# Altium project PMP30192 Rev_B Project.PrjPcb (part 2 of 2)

## Sheet PMP30192 Rev_B Modulator Schematic.SchDoc: PFC + LLC Modulator
size 431 x 279 mm; Date: Not shown in title block; ApprovedBy: Not shown in title block; CheckedBy: Not shown in title block; Author: Not shown in title block; CompanyName: Not shown in title block; DrawnBy: R. Scibilia; Engineer: Not shown in title block; Organization: Not shown in title block; Address1: Not shown in title block; Address2: Not shown in title block; Address3: Not shown in title block; Address4: Not shown in title block; DocumentNumber: 1; Revision: Use project parameter SCH_Rev; SheetNumber: 2; SheetTotal: 3; PageSetup: Record=PageOptions¦CenterHorizontal=True¦CenterVertical=True¦PrintScale=1.00¦XCorrection=1.00¦YCorrection=1.00¦PrintKind=0¦BorderSize=5000000¦LeftOffset=0¦BottomOffset=0¦Orientation=2¦PaperLength=1000¦PaperWidth=1000¦Scale=100¦PaperSource=15¦PrintQuality=600¦MediaType=1¦DitherType=10¦PaperKind=Letter¦PrintScaleMode=1
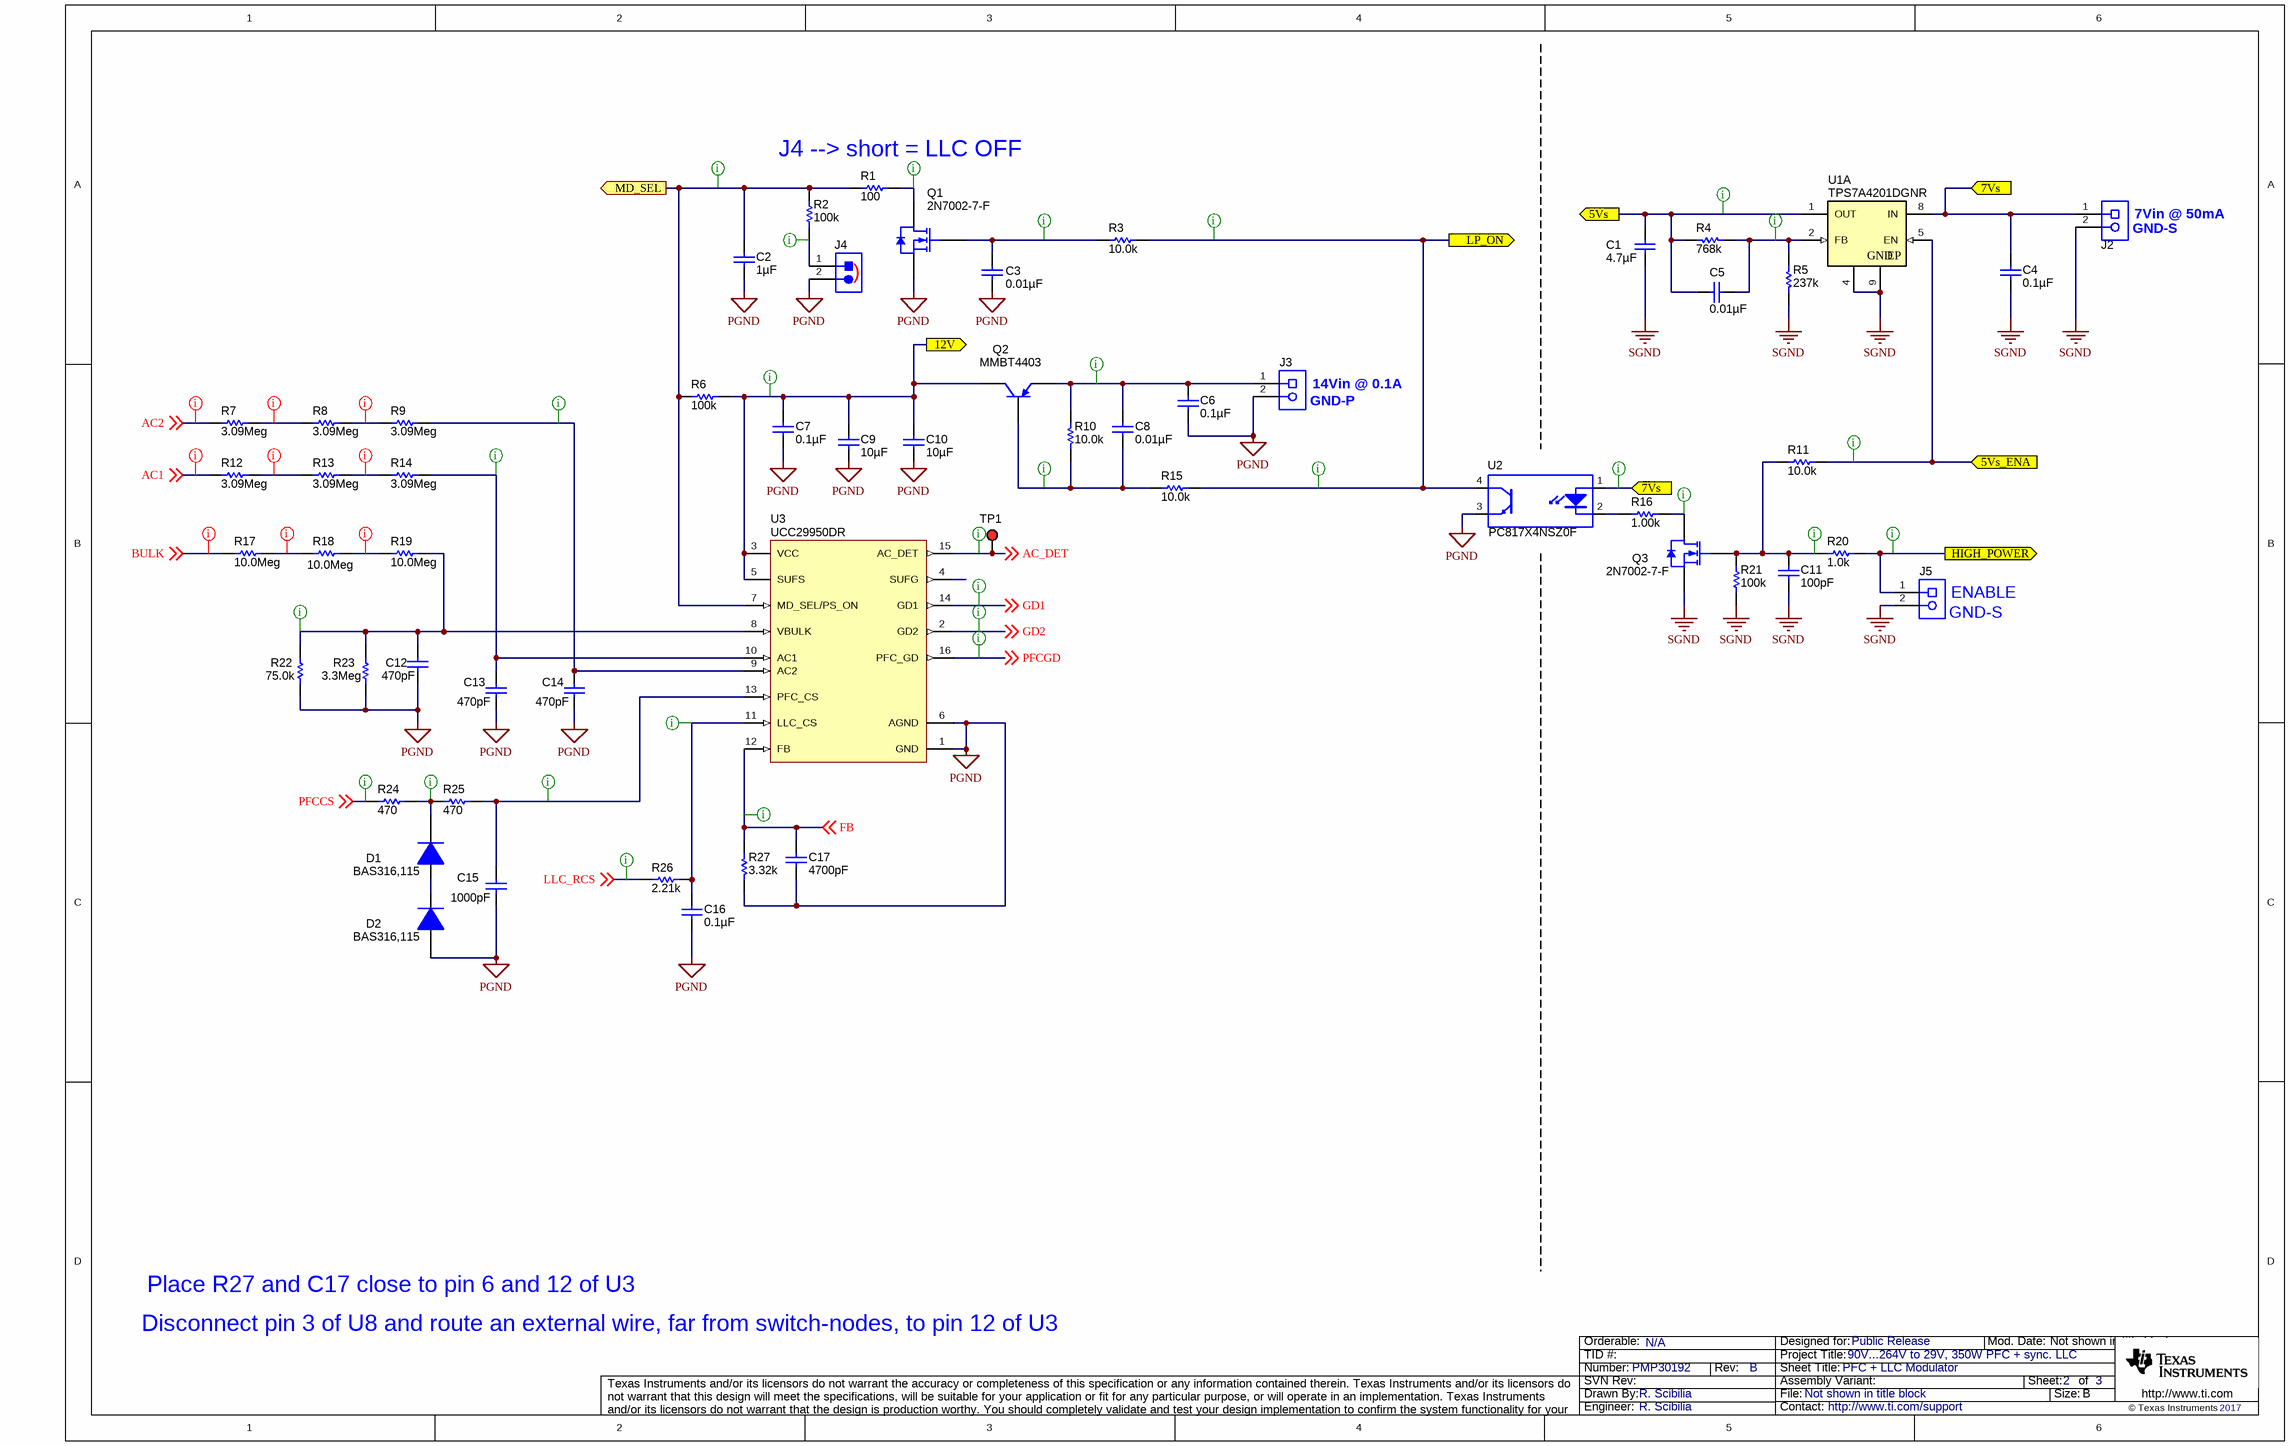
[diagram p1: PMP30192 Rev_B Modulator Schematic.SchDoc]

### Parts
C1  ValueDisplayed: 4.7µF  [0603]  (hidden comment: GRM188R61A475ME15)
C2  ValueDisplayed: 1µF  [0603]  (hidden comment: UMK107AB7105KA-T)
C3  ValueDisplayed: 0.01µF  [0603]  (hidden comment: 06031C103JAT2A)
C4  ValueDisplayed: 0.1µF  [0603]  (hidden comment: 06035C104KAT2A)
C5  ValueDisplayed: 0.01µF  [0603]  (hidden comment: 06031C103JAT2A)
C6  ValueDisplayed: 0.1µF  [0603]  (hidden comment: 06035C104KAT2A)
C7  ValueDisplayed: 0.1µF  [0603]  (hidden comment: 06035C104KAT2A)
C8  ValueDisplayed: 0.01µF  [0603]  (hidden comment: 06031C103JAT2A)
C9  ValueDisplayed: 10µF  [1206]  (hidden comment: GMK316AB7106KL)
C10  ValueDisplayed: 10µF  [1206]  (hidden comment: GMK316AB7106KL)
C11  ValueDisplayed: 100pF  [0603]  (hidden comment: 06033C101KAT2A)
C12  ValueDisplayed: 470pF  [0603]  (hidden comment: C0603C471K5RACTU)
C13  ValueDisplayed: 470pF  [0603]  (hidden comment: C0603C471K5RACTU)
C14  ValueDisplayed: 470pF  [0603]  (hidden comment: C0603C471K5RACTU)
C15  ValueDisplayed: 1000pF  [0603]  (hidden comment: C0603C102K5RACTU)
C16  ValueDisplayed: 0.1µF  [0603]  (hidden comment: 06035C104KAT2A)
C17  ValueDisplayed: 4700pF  [0603]  (hidden comment: GCM188R71H472KA37D)
D1  BAS316,115  [sod-323]
D2  BAS316,115  [sod-323]
J2  39357-0002  [Molex_39357-0002]  (value not drawn)
J3  39357-0002  [Molex_39357-0002]  (value not drawn)
J4  800-10-002-10-001000  [Mill-Max_800-10-002-10-001000]  (value not drawn)
J5  39357-0002  [Molex_39357-0002]  (value not drawn)
Q1  2N7002-7-F  [SOT-23]
Q2  MMBT4403  [SOT-23]
Q3  2N7002-7-F  [SOT-23]
R1  ValueDisplayed: 100  [0603]  (hidden comment: RC0603FR-07100RL)
R2  ValueDisplayed: 100k  [0603]  (hidden comment: CRCW0603100KFKEA)
R3  ValueDisplayed: 10.0k  [0603]  (hidden comment: CRCW060310K0FKEA)
R4  ValueDisplayed: 768k  [0603]  (hidden comment: RC0603FR-07768KL)
R5  ValueDisplayed: 237k  [0603]  (hidden comment: RC0603FR-07237KL)
R6  ValueDisplayed: 100k  [0603]  (hidden comment: CRCW0603100KFKEA)
R7  value 3.09Meg  [1206]  (hidden comment: CRCW12063M09FKEA)
R8  value 3.09Meg  [1206]  (hidden comment: CRCW12063M09FKEA)
R9  value 3.09Meg  [1206]  (hidden comment: CRCW12063M09FKEA)
R10  ValueDisplayed: 10.0k  [0603]  (hidden comment: CRCW060310K0FKEA)
R11  ValueDisplayed: 10.0k  [0603]  (hidden comment: CRCW060310K0FKEA)
R12  value 3.09Meg  [1206]  (hidden comment: CRCW12063M09FKEA)
R13  value 3.09Meg  [1206]  (hidden comment: CRCW12063M09FKEA)
R14  value 3.09Meg  [1206]  (hidden comment: CRCW12063M09FKEA)
R15  ValueDisplayed: 10.0k  [0603]  (hidden comment: CRCW060310K0FKEA)
R16  ValueDisplayed: 1.00k  [0603L]  (hidden comment: CRCW06031K00FKEA)
R17  value 10.0Meg  [1206]  (hidden comment: CRCW120610M0FKEA)
R18  value 10.0Meg  [1206]  (hidden comment: CRCW120610M0FKEA)
R19  value 10.0Meg  [1206]  (hidden comment: CRCW120610M0FKEA)
R20  ValueDisplayed: 1.0k  [0603]  (hidden comment: CRCW06031K00JNEA)
R21  ValueDisplayed: 100k  [0603]  (hidden comment: CRCW0603100KFKEA)
R22  value 75.0k  [0603]  (hidden comment: CRCW060375K0FKEA)
R23  value 3.3Meg  [0603]  (hidden comment: CRCW06033M30JNEA)
R24  value 470  [0603]  (hidden comment: RC0603FR-07470RL)
R25  value 470  [0603]  (hidden comment: RC0603FR-07470RL)
R26  ValueDisplayed: 2.21k  [0603]  (hidden comment: CRCW06032K21FKEA)
R27  value 3.32k  [0603]  (hidden comment: CRCW06033K32FKEA)
TP1  5010  [Keystone5010]  (value not drawn)
U1  TPS7A4201DGNR  [DGN0008B_N]  (part A of 2)
U2  PC817X4NSZ0F  [DIP762W60P254L460H350Q4B]
U3  UCC29950DR  [D0016A_N]

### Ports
5Vs, 5Vs_ENA, 7Vs, 12V, HIGH_POWER, LP_ON, MD_SEL

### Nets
PGND: C2.1 C3.1 C6.2 C7.2 C9.1 C10.1 C12.2 C13.2 C14.2 C15.1 C16.2 C17.2 D2.2(A) J3.2 J4.2 Q1.2(S) R22.2 R23.1 R27.2 U2.3(E) U3.1(GND) U3.6(AGND)
SGND: C1.2 C4.2 C11.2 J2.2 J5.2 Q3.2(S) R5.1 R21.1 U1.4(GND) U1.9(EP)
5Vs: C1.1 C5.2 R4.2 U1.1(OUT) ; port 5Vs
5Vs_ENA: R11.1 U1.5(EN) ; port 5Vs_ENA
7Vs: C4.1 J2.1 U1.8(IN) U2.1(A) ; port 7Vs
12V: C7.1 C9.2 C10.2 Q2.3(C) R6.1 U3.3(VCC) U3.5(SUFS) ; port 12V
AC1: R12.2 ; off-sheet AC1
AC2: R7.2 ; off-sheet AC2
AC_DET: TP1.1 U3.15(AC_DET) ; off-sheet AC_DET
BULK: R17.1 ; off-sheet BULK
FB: C17.1 R27.1 U3.12(FB) ; off-sheet FB
GD1: U3.14(GD1) ; off-sheet GD1
GD2: U3.2(GD2) ; off-sheet GD2
HIGH_POWER: J5.1 R20.1 ; port HIGH_POWER
LLC_RCS: R26.1 ; off-sheet LLC_RCS
LP_ON: R3.1 R15.1 U2.4(C) ; port LP_ON
MD_SEL: C2.2 R1.2 R2.2 R6.2 U3.7(MD_SEL/PS_ON) ; port MD_SEL
PFCCS: R24.1 ; off-sheet PFCCS
PFCGD: U3.16(PFC_GD) ; off-sheet PFCGD
NetC3_2: C3.2 Q1.1(G) R3.2
NetC5_1: C5.1 R4.1 R5.2 U1.2(FB)
NetC6_1: C6.1 C8.1 J3.1 Q2.2(E) R10.1
NetC8_2: C8.2 Q2.1(B) R10.2 R15.2
NetC11_1: C11.1 Q3.1(G) R11.2 R20.2 R21.2
NetC12_1: C12.1 R19.2 R22.1 R23.2 U3.8(VBULK)
NetC13_1: C13.1 R14.1 U3.10(AC1)
NetC14_1: C14.1 R9.1 U3.9(AC2)
NetC15_2: C15.2 R25.2 U3.13(PFC_CS)
NetC16_1: C16.1 R26.2 U3.11(LLC_CS)
NetD1_1: D1.1(K) R24.2 R25.1
NetD1_2: D1.2(A) D2.1(K)
NetJ4_1: J4.1 R2.1
NetQ1_3: Q1.3(D) R1.1
NetQ3_3: Q3.3(D) R16.1
NetR7_1: R7.1 R8.2
NetR8_1: R8.1 R9.2
NetR12_1: R12.1 R13.2
NetR13_1: R13.1 R14.2
NetR16_2: R16.2 U2.2(K)
NetR17_2: R17.2 R18.1
NetR18_2: R18.2 R19.1

Not connected (* = marked no-connect by the designer): U3 4(SUFG)

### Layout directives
rule Clearance Constraint [Clearance = 10mil]: 5Vs, 5Vs_ENA, 7Vs, 12V, AC_DET, FB, GD1, GD2, HIGH_POWER, LLC_RCS, LP_ON, MD_SEL, NetC3_2, NetC5_1, NetC6_1, NetC8_2, NetC11_1, NetC12_1, NetC13_1, NetC14_1, NetC15_2, NetC16_1, NetD1_1, NetJ4_1, NetQ1_3, NetQ3_3, PFCCS, PFCGD
rule Clearance Constraint [Clearance = 40mil]: AC1, AC2, BULK, NetR7_1, NetR8_1, NetR12_1, NetR13_1, NetR17_2, NetR18_2

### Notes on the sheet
- J4 --> short = LLC OFF
- (near J2) GND-S
- (near J2) 7Vin @ 50mA
- (near J4) )
- (near J3) GND-P
- (near J3) 14Vin @ 0.1A
- (near J5) GND-S
- (near J5) ENABLE
- Place R27 and C17 close to pin 6 and 12 of U3
- Disconnect pin 3 of U8 and route an external wire, far from switch-nodes, to pin 12 of U3

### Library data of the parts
C1 = GRM188R61A475ME15: CAP, CERM, 4.7 µF, 10 V, +/- 20%, X5R, 0603; Manufacturer: MuRata; Polarized: N; CompType: Capacitor; Value: 4.7uF; U/M: EA; Cap_F: 0.0000047; Tolerance_%: 20; Value1: Unknown; VDC_V: 10; Value2: 10V; TaMin_C: -55; TaMax_C: 85; SizeArea_mm2: 1.28; SizeAreaWB_mm2: 4.68; SizeX_mm: 1.6; SizeY_mm: 0.8; SizeZ_mm: 1; AEC Category: Q200
C2 = UMK107AB7105KA-T: CAP, CERM, 1 µF, 50 V, +/- 10%, X7R, 0603; Manufacturer: Taiyo Yuden; Polarized: N; CompType: Capacitor; Value: 1uF; U/M: EA; Cap_F: 0.000001; Tolerance_%: 10; Value1: Unknown; VDC_V: 50; Value2: 50V; TaMin_C: -55; TaMax_C: 125
C3 C5 C8 = 06031C103JAT2A: CAP, CERM, 0.01 µF, 100 V, +/- 5%, X7R, 0603; Manufacturer: AVX; Polarized: N; CompType: Capacitor; Value: 0.01uF; U/M: EA; Cap_F: 0.00000001; Tolerance_%: 5; ESR_ohm: 0.098; Value1: 0.098 ohm; VDC_V: 100; Value2: 100V; TaMin_C: -55; TaMax_C: 125
C4 C6 C7 C16 = 06035C104KAT2A: CAP, CERM, 0.1uF, 50V, +/-10%, X7R, 0603; Manufacturer: AVX; Polarized: N; CompType: Capacitor; U/M: EA; Cap_F: 0.0000001; Tolerance_%: 10; Value1: Unknown; VDC_V: 50; TaMin_C: -55; TaMax_C: 125
C9 C10 = GMK316AB7106KL: CAP, CERM, 10uF, 35V, +/-10%, X7R, 1206; Manufacturer: Taiyo Yuden; Polarized: N; CompType: Capacitor; U/M: EA; Cap_F: 0.00001; Tolerance_%: 10; Value1: Unknown; VDC_V: 35; TaMin_C: -55; TaMax_C: 125
C11 = 06033C101KAT2A: CAP, CERM, 100 pF, 25 V, +/- 10%, X7R, 0603; Manufacturer: AVX; Polarized: N; CompType: Capacitor; Value: 100pF; U/M: EA; Cap_F: 0.0000000001; Tolerance_%: 10; Value1: Unknown; VDC_V: 25; Value2: 25V; TaMin_C: -55; TaMax_C: 125; AEC Category: Q200
C12-C14 = C0603C471K5RACTU: CAP, CERM, 470pF, 50V, +/-10%, X7R, 0603; Manufacturer: Kemet; Polarized: N; CompType: Capacitor; U/M: EA; Cap_F: 0.00000000047; Tolerance_%: 10; Value1: Unknown; VDC_V: 50; TaMin_C: -55; TaMax_C: 125
C15 = C0603C102K5RACTU: CAP, CERM, 1000pF, 50V, +/-10%, X7R, 0603; Manufacturer: Kemet; Polarized: N; CompType: Capacitor; U/M: EA; Cap_F: 0.000000001; Tolerance_%: 10; Value1: Unknown; VDC_V: 50; TaMin_C: -55; TaMax_C: 125
C17 = GCM188R71H472KA37D: CAP, CERM, 4700 pF, 50 V,+/- 10%, X7R, AEC-Q200 Grade 1, 0603; Manufacturer: MuRata; Polarized: N; CompType: Capacitor; Value: 4700pF; U/M: EA; Cap_F: 0.0000000047; Tolerance_%: 10; VDC_V: 50; Value2: 50V; TaMin_C: -55; TaMax_C: 125; SizeArea_mm2: 1.28; SizeAreaWB_mm2: 4.68; SizeX_mm: 1.6; SizeY_mm: 0.8; SizeZ_mm: 1; AEC Category: Q200; AEC Qualified: Y
D1 D2 = BAS316,115: Diode, Ultrafast, 100V, 0.25A, SOD-323; Manufacturer: NXP Semiconductor; U/M: EA; Vf_V: 1.4; Value2: 1.4V; Io_A: 0.25; Vr_V: 100; TJmax_C: 150
J2 J3 J5 = 39357-0002: Terminal Block, 3.5 mm, 2x1, Tin, TH; Manufacturer: Molex; SymbolCreator: a0412235
J4 = 800-10-002-10-001000: Header, 100mil, 2x1, TH; Manufacturer: Mill-Max; SymbolCreator: a0412235
Q1 Q3 = 2N7002-7-F: MOSFET, N-CH, 60 V, 0.17 A, SOT-23; Manufacturer: Diodes Inc.; Alternate Manufacturer: None; U/M: EA; ChType: N; VdsMax_V: 60; Value1: 7.5 ohm; Rdson45_ohm: 7.5; Value2: 223 nC; QgTyp_nC: 223; Vgs_V: 20; IdsMax_A: 0.17
Q2 = MMBT4403, Fairchild Semiconductor: Transistor, PNP, 40 V, 0.6 A, SOT-23; CompType: BJT; PNP: 1; NPN: 0; Vceo_V: 40; Vcesat1_V: 0.75; IcRated_A: 0.6; Value1: 0.6 A; HfeMax: 500; TaMin_C: -55; TaMax_C: 150; U/M: EA
R1 = RC0603FR-07100RL: RES, 100, 1%, 0.1 W, 0603; Manufacturer: Yageo America; CompType: Resistor; Value: 100; Value_Code: 100R; Tolerance_%: 1; Power_W: 0.1; Value2: 0.1W; VDC_V: 150; TempCo: 200 ppm/C; SizeArea_mm2: 1.28; SizeX_mm: 1.6; SizeY_mm: 0.8; EIA_Code: E96; U/M: EA; AEC Category: Q200
R2 R6 R21 = CRCW0603100KFKEA: RES, 100 k, 1%, 0.1 W, 0603; Manufacturer: Vishay-Dale; CompType: Resistor; Value: 100k; Res_ohm: 100000; Tolerance_%: 1; Power_W: 0.1; Value2: 0.1W; VDC_V: 75; TempCo: 100 ppm/C; EIA_Code: E96; U/M: EA
R3 R10 R11 R15 = CRCW060310K0FKEA: RES, 10.0 k, 1%, 0.1 W, 0603; Manufacturer: Vishay-Dale; CompType: Resistor; Value: 10.0k; Res_ohm: 10000; Value_Code: 10k0; Tolerance_%: 1; Power_W: 0.1; Value2: 0.1W; VDC_V: 75; TempCo: 100 ppm/C; EIA_Code: E96; U/M: EA
R4 = RC0603FR-07768KL: RES, 768 k, 1%, 0.1 W, 0603; Manufacturer: Yageo America; CompType: Resistor; Value: 768k; Res_ohm: 768000; Tolerance_%: 1; Power_W: 0.1; Value2: 0.1W; VDC_V: 150; TempCo: 200 ppm/C; SizeArea_mm2: 1.28; SizeX_mm: 1.6; SizeY_mm: 0.8; EIA_Code: E96; U/M: EA; AEC Category: Q200
R5 = RC0603FR-07237KL: RES, 237 k, 1%, 0.1 W, 0603; Manufacturer: Yageo America; CompType: Resistor; Value: 237k; Res_ohm: 237000; Tolerance_%: 1; Power_W: 0.1; Value2: 0.1W; VDC_V: 150; TempCo: 200 ppm/C; SizeArea_mm2: 1.28; SizeX_mm: 1.6; SizeY_mm: 0.8; EIA_Code: E96; U/M: EA; AEC Category: Q200
R7-R9 R12-R14 = CRCW12063M09FKEA: RES, 3.09Meg ohm, 1%, 0.25W, 1206; Manufacturer: Vishay-Dale; CompType: Resistor; Res_ohm: 3090000; Value_Code: 3M09; Tolerance_%: 1; Power_W: 0.25; VDC_V: 200; TempCo: 100 ppm/C; EIA_Code: E96; U/M: EA
R16 = CRCW06031K00FKEA: RES, 1.00 k, 1%, 0.1 W, 0603; Manufacturer: Vishay-Dale; CompType: Resistor; Value: 1.00k; Res_ohm: 1000; Value_Code: 1k00; Tolerance_%: 1; Power_W: 0.1; Value2: 0.1W; VDC_V: 75; TempCo: 100 ppm/C; EIA_Code: E96; U/M: EA; AEC Category: Q200
R17-R19 = CRCW120610M0FKEA: RES, 10.0Meg ohm, 1%, 0.25W, 1206; Manufacturer: Vishay-Dale; CompType: Resistor; Res_ohm: 10000000; Value_Code: 10M0; Tolerance_%: 1; Power_W: 0.25; VDC_V: 200; TempCo: 100 ppm/C; EIA_Code: E96; U/M: EA
R20 = CRCW06031K00JNEA: RES, 1.0 k, 5%, 0.1 W, 0603; Manufacturer: Vishay-Dale; CompType: Resistor; Value: 1.0k; Res_ohm: 1000; Value_Code: 1k00; Tolerance_%: 5; Power_W: 0.1; Value2: 0.1W; VDC_V: 75; TempCo: 200 ppm/C; EIA_Code: E24; U/M: EA
R22 = CRCW060375K0FKEA: RES, 75.0k ohm, 1%, 0.1W, 0603; Manufacturer: Vishay-Dale; CompType: Resistor; Res_ohm: 75000; Value_Code: 75k0; Tolerance_%: 1; Power_W: 0.1; VDC_V: 75; TempCo: 100 ppm/C; EIA_Code: E96; U/M: EA
R23 = CRCW06033M30JNEA: RES, 3.3Meg ohm, 5%, 0.1W, 0603; Manufacturer: Vishay-Dale; CompType: Resistor; Res_ohm: 3300000; Value_Code: 3M30; Tolerance_%: 5; Power_W: 0.1; VDC_V: 75; TempCo: 200 ppm/C; EIA_Code: E24; U/M: EA
R24 R25 = RC0603FR-07470RL: RES, 470 ohm, 1%, 0.1W, 0603; Manufacturer: Yageo America; CompType: Resistor; Value_Code: 470R; Tolerance_%: 1; Power_W: 0.1; VDC_V: 150; TempCo: 200 ppm/C; U/M: EA
R26 = CRCW06032K21FKEA: RES, 2.21 k, 1%, 0.1 W, 0603; Manufacturer: Vishay-Dale; CompType: Resistor; Value: 2.21k; Res_ohm: 2210; Value_Code: 2k21; Tolerance_%: 1; Power_W: 0.1; Value2: 0.1W; VDC_V: 75; TempCo: 100 ppm/C; EIA_Code: E96; U/M: EA; AEC Category: Q200
R27 = CRCW06033K32FKEA: RES, 3.32k ohm, 1%, 0.1W, 0603; Manufacturer: Vishay-Dale; CompType: Resistor; Res_ohm: 3320; Value_Code: 3k32; Tolerance_%: 1; Power_W: 0.1; VDC_V: 75; TempCo: 100 ppm/C; EIA_Code: E96; U/M: EA
TP1 = 5010: Test Point, Multipurpose, Red, TH; Manufacturer: Keystone; CompType: Test Point Loop; U/M: EA
U1 = TPS7A4201DGNR: Single Output LDO, 50 mA, Adjustable 1.175 to 26 V Output, 7 to 28 V Input, 8-pin MSOP (DGN), -40 to 125 degC, Green (RoHS & no Sb/Br); Manufacturer: Texas Instruments; Alternate PartNumber: Equivalent; Accuracy(%): 1; Iout(Max)(A): 0.05; Iq(Typ)(mA): 0.02; SubFamily: Single Channel LDO; Vdo(Typ)(mV): 290; Vin(Max)(V): 28; Vin(Min)(V): 7; Vout Adj(Max)(V): 26; Vout Adj(Min)(V): 1.161
U2 = LTV-817: Opto-Isolator, 1 Channel, TH; Manufacturer: Sharp Electronics; CompType: OPTOCOUPLER; U/M: EA
U3 = UCC29950DR: CCM PFC and LLC Combo Controller, D0016A; Manufacturer: Texas Instruments; SymbolCreator: x0208326; CompType: IC; U/M: EA

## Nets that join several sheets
PGND: PMP30192 Rev_B PFC plus LLC Stage Schematic (30 pins), PMP30192 Rev_B Modulator Schematic (22 pins)
SGND: PMP30192 Rev_B PFC plus LLC Stage Schematic (29 pins), PMP30192 Rev_B Modulator Schematic (10 pins)
5Vs: PMP30192 Rev_B PFC plus LLC Stage Schematic (8 pins), PMP30192 Rev_B Modulator Schematic (C1.1 C5.2 R4.2 U1.1)
12V: PMP30192 Rev_B PFC plus LLC Stage Schematic (9 pins), PMP30192 Rev_B Modulator Schematic (7 pins)
AC1: PMP30192 Rev_B PFC plus LLC Stage Schematic (D3.2 L2.3 R28.2), PMP30192 Rev_B Modulator Schematic (R12.2)
AC2: PMP30192 Rev_B PFC plus LLC Stage Schematic (D3.3 L2.2 R31.1), PMP30192 Rev_B Modulator Schematic (R7.2)
AC_DET: PMP30192 Rev_B PFC plus LLC Stage Schematic (D8.1 R43.1), PMP30192 Rev_B Modulator Schematic (TP1.1 U3.15)
BULK: PMP30192 Rev_B PFC plus LLC Stage Schematic (6 pins), PMP30192 Rev_B Modulator Schematic (R17.1)
FB: PMP30192 Rev_B PFC plus LLC Stage Schematic (U8.3), PMP30192 Rev_B Modulator Schematic (C17.1 R27.1 U3.12)
GD1: PMP30192 Rev_B PFC plus LLC Stage Schematic (R55.2), PMP30192 Rev_B Modulator Schematic (U3.14)
GD2: PMP30192 Rev_B PFC plus LLC Stage Schematic (R53.2), PMP30192 Rev_B Modulator Schematic (U3.2)
LLC_RCS: PMP30192 Rev_B PFC plus LLC Stage Schematic (14 pins), PMP30192 Rev_B Modulator Schematic (R26.1)
PFCCS: PMP30192 Rev_B PFC plus LLC Stage Schematic (5 pins), PMP30192 Rev_B Modulator Schematic (R24.1)
PFCGD: PMP30192 Rev_B PFC plus LLC Stage Schematic (R34.2), PMP30192 Rev_B Modulator Schematic (U3.16)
